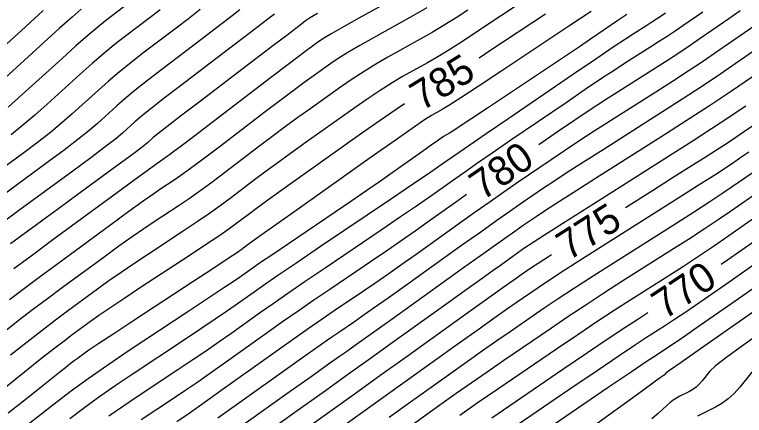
# Model space of a CAD drawing. Extents: x 2079879 to 2092887, y 778083 to 784051.
# Drawn here: x 2084103 to 2084172.8, y 780853.6 to 780891.8 of the extents above; entities that cross this region are included whole.
import ezdxf

# ---------------------------------------------------------------- set-up
doc = ezdxf.new("R2010")
doc.units = 0
doc.layers.add('DT_X_Contour_Major', color=7, linetype='Continuous')
doc.layers.add('DT_X_Contour_Minor', color=7, linetype='Continuous')

msp = doc.modelspace()

# ---------------------------------------------------------------- linework, layer by layer
at = {"layer": 'DT_X_Contour_Major'}
for points in [[(2084124.366, 780901.01), (2084123.864, 780900.641), (2084122.362, 780899.493), (2084117.995, 780896.112), (2084116.48, 780894.94), (2084115.211, 780893.96), (2084114.187, 780893.173), (2084113.409, 780892.579), (2084111.661, 780891.25), (2084110.909, 780890.652), (2084109.963, 780889.856), (2084108.825, 780888.86), (2084107.493, 780887.666), (2084103.684, 780884.216), (2084102.33, 780883.007)], [(2084131.929, 780891.946), (2084131.174, 780891.502), (2084130.792, 780891.253), (2084130.269, 780890.848), (2084129.849, 780890.526), (2084128.981, 780889.865), (2084127.665, 780888.863), (2084125.901, 780887.522), (2084120.601, 780883.492), (2084118.836, 780882.146), (2084117.517, 780881.132), (2084116.643, 780880.449), (2084116.214, 780880.097), (2084115.665, 780879.599), (2084115.329, 780879.322), (2084114.73, 780878.861), (2084113.869, 780878.219), (2084112.746, 780877.394), (2084109.403, 780874.95), (2084108.19, 780874.063), (2084107.058, 780873.235), (2084106.007, 780872.466), (2084105.037, 780871.756), (2084102.559, 780869.94)], [(2084153.729, 780891.902), (2084148.41, 780888.369), (2084147.392, 780887.698)], [(2084172.356, 780892.192), (2084171.27, 780891.441), (2084168.533, 780889.558), (2084167.479, 780888.842), (2084166.371, 780888.104), (2084165.208, 780887.346), (2084163.991, 780886.566), (2084160.671, 780884.461), (2084159.382, 780883.633), (2084158.004, 780882.731), (2084156.538, 780881.754), (2084154.984, 780880.702), (2084153.087, 780879.409)], [(2084189.119, 780891.905), (2084189.018, 780891.834), (2084188.662, 780891.588), (2084187.67, 780890.905), (2084186.04, 780889.783), (2084183.774, 780888.224), (2084176.881, 780883.482), (2084174.561, 780881.889), (2084172.771, 780880.666), (2084171.51, 780879.814), (2084170.779, 780879.333), (2084169.534, 780878.544), (2084168.836, 780878.101), (2084167.673, 780877.365), (2084166.046, 780876.335), (2084163.956, 780875.011), (2084161.393, 780873.389)], [(2084205.056, 780891.961), (2084203.752, 780891.134), (2084202.627, 780890.395), (2084201.681, 780889.743), (2084199.397, 780888.12), (2084198.433, 780887.436), (2084197.255, 780886.604), (2084195.861, 780885.623), (2084194.253, 780884.493), (2084189.679, 780881.28), (2084188.058, 780880.143), (2084186.625, 780879.143), (2084185.381, 780878.278), (2084184.326, 780877.548), (2084181.764, 780875.785), (2084180.689, 780875.043), (2084179.388, 780874.142), (2084177.86, 780873.081), (2084176.105, 780871.859), (2084171.122, 780868.388), (2084170.53, 780867.979)], [(2084140.235, 780883.308), (2084139.446, 780882.789), (2084137.916, 780881.739), (2084136.029, 780880.412), (2084130.522, 780876.502), (2084128.654, 780875.173), (2084127.178, 780874.116), (2084126.096, 780873.332), (2084125.407, 780872.82), (2084124.093, 780871.82), (2084123.445, 780871.35), (2084122.486, 780870.689), (2084121.217, 780869.837), (2084119.637, 780868.794), (2084115.01, 780865.757), (2084113.41, 780864.701), (2084112.079, 780863.809), (2084111.019, 780863.082), (2084110.228, 780862.52), (2084108.479, 780861.239), (2084107.701, 780860.656), (2084106.681, 780859.869), (2084105.417, 780858.878), (2084103.91, 780857.682), (2084099.568, 780854.222)], [(2084146.17, 780874.643), (2084145.337, 780874.053), (2084142.418, 780871.968), (2084141.27, 780871.154), (2084140.012, 780870.278), (2084138.645, 780869.339), (2084137.17, 780868.337), (2084133.09, 780865.582), (2084131.569, 780864.548), (2084130.066, 780863.513), (2084128.581, 780862.476), (2084127.114, 780861.438), (2084123.226, 780858.668), (2084121.81, 780857.666), (2084120.476, 780856.738), (2084119.226, 780855.883), (2084118.058, 780855.101), (2084115.055, 780853.115)], [(2084154.299, 780868.891), (2084154.106, 780868.768), (2084153.019, 780868.069), (2084152.427, 780867.68), (2084151.508, 780867.052), (2084150.924, 780866.644), (2084149.862, 780865.89), (2084148.321, 780864.79), (2084146.301, 780863.344), (2084140.277, 780859.029), (2084138.024, 780857.415), (2084135.78, 780855.811), (2084133.547, 780854.215), (2084131.325, 780852.628)], [(2084163.527, 780863.343), (2084162.546, 780862.723), (2084161.321, 780861.931), (2084159.718, 780860.869), (2084157.738, 780859.536), (2084155.38, 780857.933), (2084148.591, 780853.296)], [(2084173.703, 780857.992), (2084172.301, 780856.256), (2084171.76, 780855.646), (2084171.193, 780855.121), (2084170.597, 780854.68), (2084169.973, 780854.323), (2084168.274, 780853.482)]]:
    msp.add_lwpolyline(points, dxfattribs=at)
at = {"layer": 'DT_X_Contour_Minor'}
for points in [[(2084140.357, 780893.981), (2084135.894, 780891.494), (2084134.411, 780890.665), (2084133.307, 780890.041), (2084132.584, 780889.624), (2084132.241, 780889.412), (2084131.833, 780889.122), (2084131.444, 780888.833), (2084130.581, 780888.181), (2084129.245, 780887.168), (2084127.436, 780885.792), (2084121.981, 780881.641), (2084120.182, 780880.273), (2084118.879, 780879.284), (2084118.071, 780878.673), (2084117.757, 780878.441), (2084117.581, 780878.326), (2084117.234, 780878.075), (2084116.323, 780877.412), (2084114.85, 780876.334), (2084112.813, 780874.843), (2084106.63, 780870.315), (2084104.531, 780868.773), (2084102.872, 780867.544)], [(2084142.376, 780892.483), (2084141.053, 780891.737), (2084137.28, 780889.635), (2084135.963, 780888.889), (2084134.842, 780888.228), (2084133.917, 780887.652), (2084133.188, 780887.162), (2084131.505, 780885.967), (2084130.746, 780885.418), (2084129.73, 780884.665), (2084128.458, 780883.709), (2084126.929, 780882.549), (2084122.509, 780879.186), (2084120.998, 780878.042), (2084119.781, 780877.135), (2084118.857, 780876.464), (2084118.227, 780876.029), (2084116.939, 780875.184), (2084116.278, 780874.732), (2084115.262, 780874.011), (2084113.892, 780873.021), (2084112.166, 780871.762), (2084107.092, 780868.046), (2084105.312, 780866.734), (2084103.775, 780865.586), (2084102.483, 780864.602)], [(2084151.494, 780893.069), (2084147.35, 780890.316), (2084145.878, 780889.35), (2084144.57, 780888.517), (2084143.426, 780887.817), (2084142.446, 780887.25), (2084140.052, 780885.916), (2084139.068, 780885.337), (2084137.911, 780884.602), (2084136.583, 780883.71), (2084135.082, 780882.662), (2084130.85, 780879.657), (2084129.351, 780878.588), (2084128.029, 780877.632), (2084126.883, 780876.791), (2084125.914, 780876.063), (2084123.565, 780874.276), (2084122.629, 780873.581), (2084121.584, 780872.838), (2084120.43, 780872.046), (2084119.167, 780871.205), (2084115.653, 780868.899), (2084114.366, 780868.045), (2084113.14, 780867.21), (2084111.976, 780866.395), (2084110.874, 780865.6), (2084108.017, 780863.508), (2084106.872, 780862.656), (2084105.581, 780861.671), (2084104.145, 780860.551), (2084102.562, 780859.299)], [(2084105.698, 780892.225), (2084104.005, 780890.693), (2084098.892, 780886.062)], [(2084120.719, 780892.322), (2084119.578, 780891.449), (2084118.406, 780890.556), (2084115.237, 780888.147), (2084114.08, 780887.25), (2084112.985, 780886.366), (2084111.952, 780885.496), (2084110.982, 780884.638), (2084108.477, 780882.369), (2084107.482, 780881.498), (2084106.377, 780880.588), (2084105.163, 780879.639), (2084103.838, 780878.65), (2084100.157, 780875.959)], [(2084109.323, 780892.353), (2084108.453, 780891.6), (2084107.261, 780890.542), (2084105.749, 780889.18), (2084101.288, 780885.139)], [(2084127.814, 780891.901), (2084127.175, 780891.409), (2084126.227, 780890.684), (2084124.969, 780889.725), (2084123.403, 780888.533), (2084118.813, 780885.044), (2084117.251, 780883.848), (2084116.006, 780882.877), (2084115.079, 780882.131), (2084114.47, 780881.61), (2084113.269, 780880.523), (2084112.634, 780879.989), (2084111.63, 780879.206), (2084110.256, 780878.172), (2084108.512, 780876.888), (2084103.371, 780873.129), (2084101.599, 780871.831)], [(2084124.501, 780892.292), (2084123.473, 780891.503), (2084122.274, 780890.587), (2084120.904, 780889.545), (2084117.025, 780886.595), (2084115.665, 780885.549), (2084114.496, 780884.621), (2084113.516, 780883.813), (2084112.726, 780883.124), (2084110.873, 780881.446), (2084110.058, 780880.744), (2084109.004, 780879.897), (2084107.709, 780878.905), (2084106.175, 780877.769), (2084101.764, 780874.544)], [(2084146.29, 780892.262), (2084145.171, 780891.534), (2084144.041, 780890.83), (2084142.901, 780890.15), (2084141.75, 780889.494), (2084138.666, 780887.775), (2084137.515, 780887.113), (2084136.377, 780886.415), (2084135.25, 780885.681), (2084134.135, 780884.912), (2084131.178, 780882.812), (2084130.049, 780882.003), (2084128.88, 780881.148), (2084127.67, 780880.25), (2084126.421, 780879.306), (2084123.037, 780876.731), (2084121.814, 780875.812), (2084120.683, 780874.987), (2084119.644, 780874.255), (2084118.697, 780873.617), (2084116.296, 780872.041), (2084115.322, 780871.388), (2084114.201, 780870.611), (2084112.934, 780869.708), (2084111.52, 780868.681), (2084107.554, 780865.777), (2084106.092, 780864.695), (2084104.678, 780863.628), (2084103.314, 780862.577), (2084101.998, 780861.54)], [(2084158.099, 780892.153), (2084155.963, 780890.736), (2084149.47, 780886.422), (2084147.292, 780884.98), (2084145.628, 780883.89), (2084144.477, 780883.151), (2084143.839, 780882.763), (2084142.824, 780882.197), (2084142.172, 780881.786), (2084140.981, 780880.976), (2084139.249, 780879.768), (2084136.976, 780878.162), (2084130.194, 780873.347), (2084127.956, 780871.757), (2084126.328, 780870.599), (2084125.309, 780869.873), (2084124.899, 780869.577), (2084124.621, 780869.365), (2084124.26, 780869.119), (2084123.388, 780868.54), (2084122.004, 780867.627), (2084120.107, 780866.382), (2084114.367, 780862.615), (2084112.454, 780861.358), (2084111.018, 780860.409), (2084110.061, 780859.769), (2084109.582, 780859.439), (2084108.941, 780858.97), (2084108.656, 780858.756), (2084108.282, 780858.468), (2084107.819, 780858.105), (2084107.268, 780857.667), (2084105.677, 780856.399), (2084105.021, 780855.878), (2084104.246, 780855.265), (2084103.351, 780854.561), (2084102.337, 780853.765)], [(2084116.882, 780892.311), (2084115.907, 780891.568), (2084113.449, 780889.698), (2084112.494, 780888.951), (2084111.474, 780888.111), (2084110.389, 780887.178), (2084109.237, 780886.152), (2084106.08, 780883.292), (2084104.906, 780882.253), (2084103.751, 780881.279), (2084102.616, 780880.372)], [(2084161.517, 780891.869), (2084160.648, 780891.277), (2084158.04, 780889.499), (2084156.973, 780888.775), (2084155.726, 780887.936), (2084154.299, 780886.982), (2084152.693, 780885.913), (2084148.172, 780882.909), (2084146.673, 780881.914), (2084145.567, 780881.185), (2084144.855, 780880.72), (2084144.536, 780880.519), (2084144.209, 780880.338), (2084143.971, 780880.185), (2084143.501, 780879.863), (2084142.799, 780879.371), (2084141.866, 780878.711), (2084139.067, 780876.724), (2084137.939, 780875.93), (2084136.655, 780875.04), (2084135.214, 780874.053), (2084133.616, 780872.97), (2084129.147, 780869.952), (2084127.645, 780868.936), (2084126.49, 780868.152), (2084125.683, 780867.601), (2084125.224, 780867.281), (2084124.462, 780866.739), (2084123.945, 780866.384), (2084122.965, 780865.727), (2084121.523, 780864.768), (2084119.619, 780863.506), (2084113.923, 780859.739), (2084111.872, 780858.36), (2084109.989, 780857.048), (2084108.275, 780855.802), (2084106.729, 780854.623), (2084102.834, 780851.568)], [(2084165.194, 780891.989), (2084164.78, 780891.707), (2084164.345, 780891.418), (2084163.888, 780891.12), (2084163.41, 780890.814), (2084162.107, 780889.987), (2084161.384, 780889.515), (2084160.195, 780888.719), (2084158.539, 780887.598), (2084156.416, 780886.154), (2084150.133, 780881.87), (2084148.042, 780880.444), (2084146.484, 780879.379), (2084145.458, 780878.674), (2084144.963, 780878.331), (2084144.355, 780877.896), (2084143.842, 780877.542), (2084142.761, 780876.806), (2084141.11, 780875.688), (2084138.891, 780874.188), (2084132.214, 780869.679), (2084129.939, 780868.139), (2084128.12, 780866.902), (2084126.759, 780865.967), (2084125.854, 780865.334), (2084124.05, 780864.049), (2084123.233, 780863.478), (2084122.136, 780862.731), (2084120.757, 780861.806), (2084119.098, 780860.705), (2084114.3, 780857.531), (2084112.572, 780856.369), (2084110.986, 780855.264), (2084109.542, 780854.214), (2084108.24, 780853.221)], [(2084168.769, 780892.085), (2084166.863, 780890.773), (2084166.13, 780890.274), (2084165.358, 780889.761), (2084164.548, 780889.233), (2084163.7, 780888.69), (2084161.389, 780887.224), (2084160.383, 780886.574), (2084159.1, 780885.725), (2084157.539, 780884.676), (2084155.7, 780883.428), (2084150.427, 780879.833), (2084148.614, 780878.594), (2084147.131, 780877.575), (2084145.976, 780876.774), (2084145.15, 780876.192), (2084143.387, 780874.932), (2084142.556, 780874.348), (2084141.386, 780873.542), (2084139.878, 780872.514), (2084138.03, 780871.263), (2084132.652, 780867.631), (2084130.754, 780866.344), (2084129.093, 780865.208), (2084127.67, 780864.222), (2084126.484, 780863.386), (2084123.638, 780861.358), (2084122.521, 780860.572), (2084121.306, 780859.734), (2084119.992, 780858.845), (2084118.578, 780857.903), (2084114.678, 780855.323), (2084113.273, 780854.379), (2084111.983, 780853.48)], [(2084173.771, 780890.798), (2084170.203, 780888.343), (2084168.829, 780887.409), (2084167.384, 780886.447), (2084165.868, 780885.459), (2084164.281, 780884.443), (2084159.953, 780881.697), (2084158.38, 780880.693), (2084156.909, 780879.737), (2084155.538, 780878.832), (2084154.268, 780877.976), (2084151.017, 780875.759), (2084149.759, 780874.895), (2084148.424, 780873.966), (2084147.012, 780872.973), (2084145.523, 780871.914), (2084141.45, 780869.003), (2084139.983, 780867.96), (2084138.637, 780867.014), (2084137.413, 780866.165), (2084136.309, 780865.412), (2084133.528, 780863.534), (2084132.384, 780862.753), (2084131.039, 780861.819), (2084129.493, 780860.731), (2084127.744, 780859.491), (2084122.814, 780855.978), (2084121.098, 780854.761), (2084119.646, 780853.742), (2084118.46, 780852.921)], [(2084176.271, 780890.154), (2084171.872, 780887.128), (2084170.179, 780885.976), (2084168.397, 780884.79), (2084166.528, 780883.571), (2084164.571, 780882.319), (2084159.235, 780878.934), (2084157.379, 780877.752), (2084155.813, 780876.744), (2084154.538, 780875.91), (2084153.552, 780875.25), (2084151.312, 780873.722), (2084150.331, 780873.046), (2084149.071, 780872.162), (2084147.53, 780871.072), (2084145.71, 780869.775), (2084140.482, 780866.039), (2084138.697, 780864.767), (2084137.263, 780863.75), (2084136.18, 780862.99), (2084135.449, 780862.487), (2084133.966, 780861.485), (2084133.199, 780860.957), (2084132.012, 780860.124), (2084130.404, 780858.986), (2084128.375, 780857.543), (2084122.402, 780853.288)], [(2084173.542, 780885.912), (2084171.528, 780884.543), (2084169.41, 780883.134), (2084167.188, 780881.684), (2084164.861, 780880.195), (2084158.517, 780876.171), (2084156.378, 780874.811), (2084154.718, 780873.75), (2084153.537, 780872.987), (2084152.836, 780872.524), (2084151.606, 780871.685), (2084150.903, 780871.196), (2084149.718, 780870.358), (2084148.049, 780869.171), (2084145.897, 780867.636), (2084139.514, 780863.075), (2084137.411, 780861.573), (2084135.889, 780860.487), (2084134.948, 780859.816), (2084134.588, 780859.561), (2084134.404, 780859.437), (2084134.015, 780859.162), (2084132.985, 780858.43), (2084131.315, 780857.241), (2084129.005, 780855.596), (2084121.991, 780850.598)], [(2084172.878, 780883.11), (2084170.424, 780881.477), (2084167.848, 780879.797), (2084165.151, 780878.071), (2084157.799, 780873.408), (2084155.376, 780871.87), (2084153.622, 780870.756), (2084152.537, 780870.065), (2084152.12, 780869.798), (2084151.901, 780869.648), (2084151.767, 780869.555), (2084151.53, 780869.387), (2084151.189, 780869.145), (2084150.745, 780868.828), (2084149.424, 780867.883), (2084148.74, 780867.394), (2084147.678, 780866.634), (2084146.239, 780865.603), (2084144.422, 780864.302), (2084139.074, 780860.471), (2084137.002, 780858.988), (2084134.798, 780857.411), (2084132.461, 780855.742), (2084129.992, 780853.979), (2084123.23, 780849.155)], [(2084173.188, 780878.707), (2084172.612, 780878.308), (2084171.742, 780877.702), (2084171.147, 780877.307), (2084170.015, 780876.578), (2084168.346, 780875.513), (2084166.139, 780874.114), (2084159.538, 780869.936), (2084157.275, 780868.498), (2084155.433, 780867.318), (2084154.014, 780866.395), (2084153.018, 780865.73), (2084150.925, 780864.301), (2084149.996, 780863.658), (2084148.78, 780862.804), (2084147.276, 780861.736), (2084145.485, 780860.456), (2084140.325, 780856.76), (2084138.395, 780855.378), (2084136.474, 780854.003), (2084134.561, 780852.636)], [(2084173.485, 780876.696), (2084171.587, 780875.374), (2084170.7, 780874.773), (2084169.461, 780873.96), (2084167.872, 780872.938), (2084165.932, 780871.704), (2084160.29, 780868.133), (2084158.286, 780866.856), (2084156.504, 780865.706), (2084154.945, 780864.68), (2084153.609, 780863.781), (2084150.341, 780861.55), (2084149.068, 780860.673), (2084147.698, 780859.717), (2084146.232, 780858.682), (2084144.669, 780857.568), (2084140.374, 780854.491), (2084138.767, 780853.34)], [(2084174.358, 780875.084), (2084171.432, 780873.045), (2084170.252, 780872.238), (2084168.908, 780871.343), (2084167.399, 780870.362), (2084165.725, 780869.294), (2084161.042, 780866.329), (2084159.298, 780865.215), (2084157.576, 780864.093), (2084155.876, 780862.966), (2084154.199, 780861.832), (2084149.758, 780858.798), (2084148.14, 780857.688), (2084146.616, 780856.631), (2084145.187, 780855.629), (2084143.853, 780854.68), (2084140.422, 780852.222)], [(2084175.232, 780873.471), (2084171.277, 780870.717), (2084169.805, 780869.703), (2084168.354, 780868.726), (2084166.925, 780867.786), (2084165.518, 780866.883), (2084161.794, 780864.526), (2084160.309, 780863.573), (2084158.647, 780862.481), (2084156.807, 780861.251), (2084154.79, 780859.882), (2084149.174, 780856.047), (2084147.211, 780854.703), (2084145.534, 780853.545)], [(2084176.978, 780870.247), (2084170.967, 780866.06), (2084168.91, 780864.633), (2084167.247, 780863.491), (2084165.978, 780862.634), (2084165.104, 780862.063), (2084163.298, 780860.92), (2084162.332, 780860.29), (2084160.789, 780859.257), (2084158.669, 780857.822), (2084155.971, 780855.984), (2084148.007, 780850.545)], [(2084177.851, 780868.635), (2084170.812, 780863.732), (2084168.462, 780862.098), (2084166.693, 780860.873), (2084165.505, 780860.058), (2084164.897, 780859.652), (2084164.05, 780859.116), (2084163.359, 780858.658), (2084161.921, 780857.686), (2084159.736, 780856.2), (2084156.804, 780854.2), (2084147.99, 780848.181)], [(2084178.885, 780867.093), (2084171.104, 780861.681), (2084168.548, 780859.901), (2084166.713, 780858.619), (2084165.601, 780857.835), (2084165.211, 780857.55), (2084165.133, 780857.454), (2084165.103, 780857.42), (2084165.072, 780857.391), (2084165.039, 780857.367), (2084165.005, 780857.347), (2084164.911, 780857.301), (2084164.876, 780857.282), (2084164.842, 780857.26), (2084164.809, 780857.235), (2084164.777, 780857.206), (2084164.693, 780857.127), (2084164.255, 780856.805), (2084163.004, 780855.897), (2084160.939, 780854.404), (2084158.061, 780852.325)], [(2084174.83, 780861.81), (2084172.688, 780860.301), (2084171.078, 780859.124), (2084170.001, 780858.281), (2084169.457, 780857.771), (2084168.717, 780856.855), (2084168.432, 780856.533), (2084168.132, 780856.256), (2084167.818, 780856.023), (2084167.489, 780855.835), (2084166.592, 780855.391), (2084166.26, 780855.21), (2084165.937, 780855), (2084165.624, 780854.761), (2084165.319, 780854.492), (2084164.518, 780853.736), (2084163.896, 780853.229)]]:
    msp.add_lwpolyline(points, dxfattribs=at)

# ---------------------------------------------------------------- texts
at = {"layer": 'DT_X_Contour_Major'}
for s, rotation, p in [('785', 31.51988, (2084141.893, 780882.581)), ('780', 34.56141, (2084147.708, 780874.024)), ('775', 32.37866, (2084155.94, 780868.278)), ('770', 33.50087, (2084165.111, 780862.646))]:
    msp.add_text(s, height=2.8, rotation=rotation, dxfattribs=at).set_placement(p)

doc.saveas('drawing.dxf')
